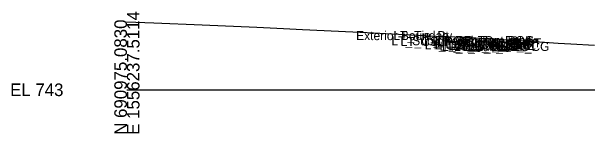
# Model space of a CAD drawing. Extents: x -26 to 303, y -10 to 5027.
# Drawn here: x -25.7 to 102.6, y 3490.3 to 3517.4 of the extents above; entities that cross this region are included whole.
import ezdxf

# ---------------------------------------------------------------- set-up
doc = ezdxf.new("R2010")
doc.units = 0
for name, color, linetype in [('Default', 7, 'Continuous'), ('Exist Cross Section Cell', 7, 'Continuous'), ('Exist XS Ground Line', 7, 'Continuous')]:
    doc.layers.add(name, color=color, linetype=linetype)

msp = doc.modelspace()

# ---------------------------------------------------------------- linework, layer by layer
at = {"layer": 'Exist Cross Section Cell'}
msp.add_line((0, 3500), (150, 3500), dxfattribs=at)
at = {"layer": 'Exist XS Ground Line'}
msp.add_lwpolyline([(0, 3515.12), (5.98, 3514.89), (16.76, 3514.44), (28.94, 3513.89), (34.89, 3513.6), (39.14, 3513.4), (53.47, 3512.71), (68.87, 3511.94), (70.81, 3511.85), (75.23, 3511.65), (77.58, 3511.51), (82.93, 3511.25), (86.11, 3511.02), (89.62, 3510.8), (92.96, 3510.59), (96.02, 3510.37), (98.89, 3510.19), (104.15, 3509.92)], dxfattribs=at)

# ---------------------------------------------------------------- texts
at = {"layer": 'Default'}
for s, height, p in [('Exterior Boundary', 2, (51.05, 3511.03)), ('LT_Tie_Pt', 2, (59.35, 3511.03)), ('LT_Sub_Trench_Out_DLT', 2, (58.92, 3509.9)), ('LT_CSLP_Pnt', 2, (60.95, 3509.75)), ('LT_CG_Top_Face', 2, (68.03, 3509.94)), ('LT_CG_Top_BOC', 2, (68.56, 3509.94)), ('LT_CG1_Shelf_Out', 2, (66.33, 3508.96)), ('LT_CG_Bot_BOC', 2, (68.59, 3508.95)), ('LT_CG_Top_Gut', 2, (69.01, 3509.44)), ('LT_Sub_OEOP', 2, (69.64, 3508.72)), ('LT_Sub_OEOT_CG', 2, (70.15, 3508.62)), ('LT_CG_Bot_IE', 2, (72.69, 3508.87)), ('LT_Sub_OEOT', 2, (72.85, 3508.58)), ('LT_PV2_OEOT', 2, (72.95, 3509.21)), ('LT_PV3_OEOT', 2, (72.95, 3508.96)), ('LT_PV1_OEOT', 2, (73.52, 3509.46)), ('-', 0.0001, (0, 3500)), ('-', 0.0001, (0, 3500))]:
    msp.add_text(s, height=height, dxfattribs=at).set_placement(p)
at = {"layer": 'Exist Cross Section Cell'}
for s, p in [('E 1556237.5114', (2.8, 3490)), ('N 690975.0830', (0, 3490))]:
    msp.add_text(s, height=2.8, rotation=90, dxfattribs=at).set_placement(p)
msp.add_text('EL 743', height=2.8, dxfattribs=at).set_placement((-26, 3498.6))

doc.saveas('drawing.dxf')
